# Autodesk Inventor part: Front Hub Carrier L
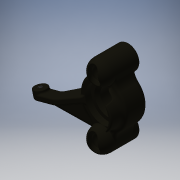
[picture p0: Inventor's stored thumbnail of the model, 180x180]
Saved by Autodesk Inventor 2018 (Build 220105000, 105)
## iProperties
Shininess: 4.0
Length Units: 11272
Angle Units: 11279
Time Units: 11290
Mass Units: 11286
Length Display Precision: 3
Angle Display Precision: 2
Compacted: True
Company: Autodesk
Created: 2000-12
Part Number: Front Hub Carrier L
Document SubType Name: Modeling
Designer: Autodesk, Inc.
Project: Inventor Samples
User Status: IN PROGRESS
Material: Stiffzel
Density: 1.28 g/cm^3
Mass: 9.69759 g
Surface Area: 49.8526 cm^2
Volume: 7.57624 cm^3
Appearance: Stiffzel
Density: 1.28
Volumn: 7.576389013112748
Area: 49.85339250399974
PropertySet Name: Model Information
Control State: 0
Master: False
Checked Out: False
Last Check In Date: 2002-03-02
Last Check In By: Kevin.s
Author: Autodesk, Inc.
Revision Number: A
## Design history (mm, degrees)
sketch "Sketch1"
  geometry: L1 (6.351, 13.207)-(6.351, 8.171); L2 (-6.349, 13.207)-(-6.349, 8.171); L3 (-6.349, -18.861)-(-6.349, -13.826); L4 (6.351, -18.861)-(6.351, -13.826); C1 r 22.384 at (0.001, -2.827); A1 r 6.35 centre (0.001, 13.207) between (6.351, 13.207) and (-6.349, 13.207); A2 r 6.35 centre (0.001, -18.861) between (-6.349, -18.861) and (6.351, -18.861); A3 r 12.7 centre (0.001, -2.827) between (-6.349, 8.171) and (-6.349, -13.826); A4 r 12.7 centre (0.001, -2.827) between (6.351, -13.826) and (6.351, 8.171)
  constraints: 8 end point, 8 point on circle, 6 tangent, 5 centre point, 4 vertical alignment, 2 equal radius, 2 parallel, 2 vertical, 1 coincident, 1 other
  dimensions: "d0" = 44.7675 diameter of C1; "d2" = 12.7 diameter of A1; "d66" = 12.7 radius of A4
extrude "Extrusion1" new body sketch "Sketch1" distance "d4" = 14.2875; taper "d5" = 0 deg
fillet "Fillet1" dims "d6" = 6.35
workplane "Work Plane1"
sketch "Sketch3"
  geometry: L1 (-16.813, 46.821)-(-4.113, 46.821); A1 r 6.35 centre (-10.463, 46.821) between (-4.139, 47.402) and (-16.786, 47.399); A2 r 4.128 centre (-10.463, 46.821) between (-6.335, 46.821) and (-14.59, 46.821); A3 r 6.35 centre (-10.463, 46.821) between (-4.113, 46.821) and (-16.813, 46.821); 3 further points
  constraints: 9 point on circle, 3 centre point, 2 coincident, 2 end point, 2 point on line, 1 horizontal, 1 midpoint, 3 other
  dimensions: "d12" = 8.255 diameter of A2
revolve "Revolution1" sketch "Sketch3" stored, may be unused: angle "d11" = 180 deg
sketch "Sketch4"
  geometry: L1 (-16.838, 41.279)-(-4.138, 41.279); A1 r 6.35 centre (-10.488, 41.279) between (-4.155, 41.746) and (-16.821, 41.747); A2 r 4.128 centre (-10.488, 41.279) between (-6.361, 41.279) and (-14.616, 41.279); A3 r 6.35 centre (-10.488, 41.279) between (-4.138, 41.279) and (-16.838, 41.279); A4 r 6.35 centre (-10.488, 41.279) between (-5.281, 37.644) and (-15.677, 37.618); 3 further points
  constraints: 11 point on circle, 4 centre point, 3 coincident, 2 concentric, 2 end point, 2 point on line, 1 horizontal, 1 midpoint, 2 other
  dimensions: "d14" = 8.255 diameter of A2
revolve "Revolution2" sketch "Sketch4" stored, may be unused: angle "d13" = 180 deg
sketch "Sketch5"
  geometry: C1 r 9.525 at (0.001, -2.827); 3 further points
  constraints: 1 centre point, 1 coincident, 1 other
  dimensions: "d15" = 19.05 diameter of C1
extrude "Extrusion3" cut sketch "Sketch5" distance "d16" = 3.175; taper "d17" = 0 deg
sketch "Sketch6"
  geometry: C1 r 6.35 at (-0.001, -2.827); A1 r 12.7 centre (-0.001, -2.827) between (8.466, -12.293) and (8.466, 6.639) reference
  constraints: 1 centre point, 1 concentric
  dimensions: "d80" = 12.7 diameter of C1
extrude "Extrusion4" cut sketch "Sketch6" distance "d18" = 4.7625; taper "d19" = 0 deg
workplane "Work Plane2"
  workaxis "Work Axis1"
workplane "Work Plane3"
  workaxis "Work Axis2"
workplane "Work Plane4"
  workaxis "Work Axis3"
sketch "Sketch7"
  geometry: C1 r 4.127 at (0, 0) reference; C2 r 4.128 at (0, -32.068) reference
extrude "Extrusion5" cut sketch "Sketch7" extent not by distance; stored distance "d24" = 3.175 (= d16); taper "d25" = 0 deg
sketch "Sketch8"
  geometry: L1 (4.082, -12.495)-(-4.173, -12.495); L2 (2.685, -15.591)-(2.685, -18.228); L3 (-2.776, -15.591)-(-2.776, -18.228); L4 (-12.303, -10.908)-(-12.303, -6.145) reference; L5 (-4.173, 1.792)-(4.082, 1.792) reference; A1 r 4.127 centre (-0.046, -12.495) between (-4.173, -12.495) and (4.082, -12.495); A2 r 6.35 centre (-0.046, -12.495) between (-6.396, -12.511) and (6.304, -12.511); A3 r 6.35 centre (-0.046, -12.495) between (-6.396, -12.495) and (6.304, -12.495) reference; A4 r 4.127 centre (-0.046, -12.495) between (-4.173, -12.495) and (4.082, -12.495) reference
  constraints: 9 point on circle, 6 end point, 3 concentric, 3 parallel, 2 centre point, 1 coincident, 1 midpoint, 1 perpendicular
  dimensions: "d27" = 5.461 distance between parallel lines of L2 L3
revolve "Revolution3" sketch "Sketch8" stored, may be unused: angle "d26" = 100 deg
sketch "Sketch9"
  geometry: L1 (5.053, -12.336)-(-3.202, -12.336); L2 (3.656, -15.432)-(3.656, -18.069); L3 (-1.805, -15.432)-(-1.805, -18.069); L4 (-3.202, 1.951)-(5.053, 1.951) reference; A1 r 4.128 centre (0.926, -12.336) between (-3.202, -12.336) and (5.053, -12.336); A2 r 6.35 centre (0.926, -12.336) between (-5.424, -12.336) and (7.276, -12.336); A3 r 4.128 centre (0.926, -12.336) between (-3.202, -12.336) and (5.053, -12.336) reference; A4 r 6.35 centre (0.926, -12.336) between (-5.424, -12.336) and (7.276, -12.336) reference
  constraints: 9 point on circle, 6 end point, 4 concentric, 3 parallel, 2 centre point, 1 midpoint, 1 perpendicular
  dimensions: "d29" = 5.461 distance between parallel lines of L2 L3
revolve "Revolution4" sketch "Sketch9" stored, may be unused: angle "d28" = 100 deg
fillet "Fillet3" dims "d30" = 2.54
sketch "Sketch16"
  geometry: L1 (-6.351, 13.207)-(-6.351, 11.372) reference; L2 (-6.351, -17.026)-(-6.351, -18.861) reference; L3 (6.349, -18.861)-(6.349, -17.026) reference; L4 (6.349, 11.372)-(6.349, 13.207) reference; C1 r 6.35 at (-0.001, -2.827) reference; C2 r 6.35 at (-0.001, 13.207); C3 r 6.35 at (-0.001, -18.861); A1 r 6.35 centre (-12.701, 11.372) between (-8.468, 6.639) and (-6.351, 11.372) reference; A2 r 12.7 centre (-0.001, -2.827) between (-8.468, 6.639) and (-8.468, -12.293) reference; A3 r 6.35 centre (-12.701, -17.026) between (-6.351, -17.026) and (-8.468, -12.293) reference; A4 r 6.35 centre (-0.001, -18.861) between (-6.351, -18.861) and (6.349, -18.861) reference; A5 r 6.35 centre (12.699, -17.026) between (8.466, -12.293) and (6.349, -17.026) reference; A6 r 12.7 centre (-0.001, -2.827) between (8.466, -12.293) and (8.466, 6.639) reference; A7 r 6.35 centre (12.699, 11.372) between (6.349, 11.372) and (8.466, 6.639) reference; A8 r 6.35 centre (-0.001, 13.207) between (6.349, 13.207) and (-6.351, 13.207) reference
  constraints: 2 centre point, 2 coincident, 2 tangent
extrude "Extrusion11" cut sketch "Sketch16" distance "d76" = 1.5875; taper "d77" = 0 deg
chamfer "Chamfer2" distance "d42" = 0.381; stored, may be unused: second distance "d43" = 0.381, angle "d148" = 45 deg
sketch "Sketch10"
  geometry: C1 r 6.032 at (0, 0); C2 r 6.35 at (0, 0) reference
  constraints: 1 centre point, 1 coincident
  dimensions: "d44" = 12.065 diameter of C1
extrude "Extrusion6" cut sketch "Sketch10" extent not by distance; stored distance "d45" = 3.175 (= d16); taper "d46" = 0 deg
fillet "Fillet13" dims "d47" = 0.381
fillet "Fillet31" dims "d94" = 1.5875
fillet "Fillet32" dims "d95" = 0.381
fillet "Fillet33" dims "d96" = 0.3556
chamfer "Chamfer4" distance "d97" = 1.5875; stored, may be unused: second distance "d98" = 1.5875, angle "d149" = 45 deg
thread "Thread1" dims "d99" = 8.001, "d100" = 0
thread "Thread2" dims "d101" = 8.001, "d102" = 0
workplane "Work Plane5"
  workaxis "Work Axis4"
  workaxis "Work Axis5"
fillet "Fillet34" dims "d105" = 3.175
fillet "Fillet35" dims "d106" = 0.8128
fillet "Fillet36" dims "d107" = 0.8128
fillet "Fillet37" dims "d108" = 0.8128
sketch "Sketch19"
  geometry: L1 (-1.2, 14.287)-(9.525, 14.287) reference; L2 (11.957, 2.722)-(21.982, 14.669); L3 (21.982, 14.669)-(30.48, 14.668); L4 (30.48, 21.526)-(19.863, 21.526); L5 (19.863, 21.526)-(9.525, 14.287); L6 (9.525, 14.287)-(9.525, 1.587); L7 (0, -4.305)-(0, 25.832) reference; A1 r 3.175 centre (9.525, 4.763) between (9.525, 1.587) and (12.7, 4.763) reference; A2 r 3.429 centre (30.48, 18.098) between (30.48, 14.668) and (30.48, 21.526); 1 further point
  constraints: 10 end point, 3 point on circle, 3 tangent, 2 parallel, 1 centre point, 1 perpendicular
  dimensions: "d109" = 3.429 radius of A2; "d110" = 30.48 distance from line of A2.centre L7; "d111" = 55 deg angle of L5 L6; "d112" = 3.81 distance from line of L1 A2.centre; "d113" = 15 deg angle of L5 L2
extrude "Extrusion13" join sketch "Sketch19" stored distance "d114" = 3.175; taper "d115" = 0 deg
fillet "Fillet38" dims "d116" = 3.175
fillet "Fillet39" dims "d117" = 6.35
sketch "Sketch20"
  geometry: A1 r 3.429 centre (-30.48, -18.098) between (-30.48, -14.668) and (-30.48, -21.526) reference; 1 further point
  constraints: 1 coincident, 1 vertical alignment, 2 other
extrude "Extrusion14" join sketch "Sketch20" distance "d118" = 1.5875; taper "d119" = 0 deg
fillet "Fillet41" dims "d121" = 0.8128
fillet "Fillet42" dims "d122" = 0.8128
fillet "Fillet43" dims "d123" = 0.8128
sketch "Sketch21"
  geometry: C1 r 3.429 at (0, 0) reference
hole "Hole2" sketch "Sketch21" at (0, 0) diameter "d124" = 2.159; stored, may be unused: countersink angle "d128" = 60 deg, drill point angle "d130" = 118 deg; dims "d125" = 12.7, "d126" = 9.525, "d127" = 6.35, "d129" = 19.05
fillet "Fillet44" dims "d131" = 0.381
workplane "Work Plane6"
sketch "Sketch22"
  geometry: L1 (4.12, 15.883)-(-6.808, 2.04)
  constraints: 2 end point
feature "Rib1" sketch "Sketch22" dims "d132" = 2.54, "d133" = 2.54
fillet "Fillet45" dims "d134" = 1.27
fillet "Fillet46" dims "d135" = 1.27
sketch "Sketch23"
  geometry: A1 r 11.112 centre (0.001, -2.827) between (7.409, -11.11) and (7.409, 5.456) reference; A2 r 9.525 centre (0.001, -2.827) between (1.287, -12.265) and (1.287, 6.611) reference; A3 r 8.001 centre (3.113, -2.827) between (5.849, -10.346) and (5.849, 4.691)
  constraints: 4 point on circle, 1 centre point, 1 tangent, 1 vertical alignment
  dimensions: "d136" = 8.001 radius of A3
extrude "Extrusion15" join sketch "Sketch23" distance "d137" = 6.35; taper "d138" = 0 deg
fillet "Fillet47" dims "d140" = 3.175
fillet "Fillet48" dims "d141" = 0.8128
fillet "Fillet49" dims "d142" = 0.381
fillet "Fillet50" dims "d143" = 0.381
fillet "Fillet51" dims "d144" = 0.381
fillet "Fillet52" dims "d147" = 0.8128
body "Solid1"
feature "FaceDraft2" dims angle "d139" = 2.5 deg
other parameters: "d3" = 25.4, "d20" = 0, "d21" = 15 deg, "d22" = 0, "d23" = 0, "d48" = 0, "d49" = 0
